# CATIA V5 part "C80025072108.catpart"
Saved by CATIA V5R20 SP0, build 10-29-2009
Part number: C80025072108
Source: Unknown
Property "A": "90"
Property "ARTICLENO": "C80025072108"
Property "B": "45"
Property "BOMINFO": "C80025072108"
Property "C": "130"
Property "CA": "C80025072108"
Property "D1": "170"
Property "DES": "ROTATING EYEBOLT WITH RING Ton 25 M72x108"
Property "E": "165"
Property "H": "338"
Property "L": "108"
Property "LINA": "C80025072108"
Property "NB": "C80025072108"
Property "NBSYN": "$CODE."
Property "NN": "C800"
Property "NT": "Rotating eyebolt with ring"
Property "SIZE": "M72"
Property "SUPPLIER": "CF"
Property "SW": "134"
Property "WEIGHT": "29000"
Property "WLL": "25.00"
Bounding box of the stored display mesh (mm): x -90 to 90, y -108 to 383, z -85 to 85
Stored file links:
  C:\Users\Utente\Desktop\3D files 800\C80025072108.catpart
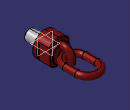
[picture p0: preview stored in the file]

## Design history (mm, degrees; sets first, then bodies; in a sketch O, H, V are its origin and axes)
Body1 "Geometry.1" (main body)
  Solid1 "C80025072108.catpart": solid without history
